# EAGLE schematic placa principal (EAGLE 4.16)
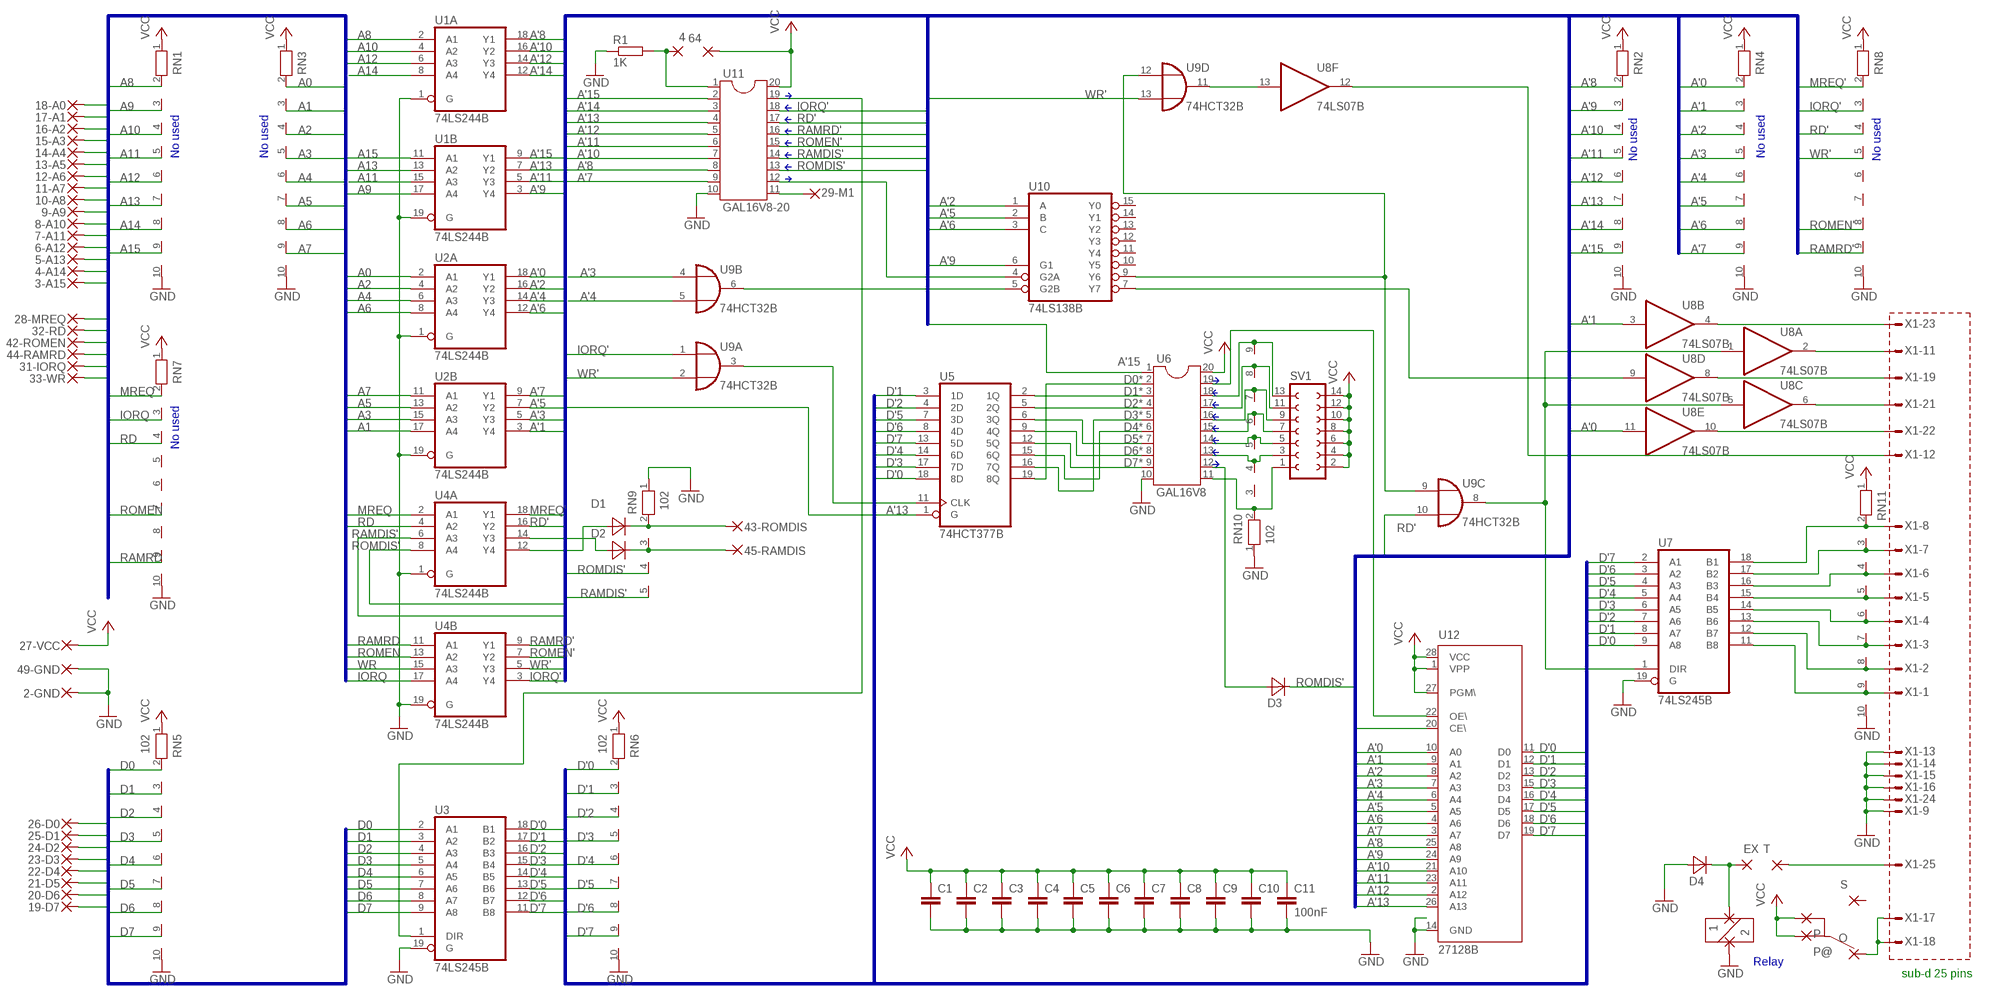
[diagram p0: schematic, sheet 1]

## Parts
1  1,27-REDONDO0.8  [1,27/0,8-REDONDO]
2  1,27-REDONDO0.8  [1,27/0,8-REDONDO]
2-GND  1,27-REDONDO0.8  [1,27/0,8-REDONDO]
3-A15  1,27-REDONDO0.8  [1,27/0,8-REDONDO]
4  1,27-REDONDO0.8  [1,27/0,8-REDONDO]
4-A14  1,27-REDONDO0.8  [1,27/0,8-REDONDO]
5-A13  1,27-REDONDO0.8  [1,27/0,8-REDONDO]
6-A12  1,27-REDONDO0.8  [1,27/0,8-REDONDO]
7-A11  1,27-REDONDO0.8  [1,27/0,8-REDONDO]
8-A10  1,27-REDONDO0.8  [1,27/0,8-REDONDO]
9-A9  1,27-REDONDO0.8  [1,27/0,8-REDONDO]
10-A8  1,27-REDONDO0.8  [1,27/0,8-REDONDO]
11-A7  1,27-REDONDO0.8  [1,27/0,8-REDONDO]
12-A6  1,27-REDONDO0.8  [1,27/0,8-REDONDO]
13-A5  1,27-REDONDO0.8  [1,27/0,8-REDONDO]
14-A4  1,27-REDONDO0.8  [1,27/0,8-REDONDO]
15-A3  1,27-REDONDO0.8  [1,27/0,8-REDONDO]
16-A2  1,27-REDONDO0.8  [1,27/0,8-REDONDO]
17-A1  1,27-REDONDO0.8  [1,27/0,8-REDONDO]
18-A0  1,27-REDONDO0.8  [1,27/0,8-REDONDO]
19-D7  1,27-REDONDO0.8  [1,27/0,8-REDONDO]
20-D6  1,27-REDONDO0.8  [1,27/0,8-REDONDO]
21-D5  1,27-REDONDO0.8  [1,27/0,8-REDONDO]
22-D4  1,27-REDONDO0.8  [1,27/0,8-REDONDO]
23-D3  1,27-REDONDO0.8  [1,27/0,8-REDONDO]
24-D2  1,27-REDONDO0.8  [1,27/0,8-REDONDO]
25-D1  1,27-REDONDO0.8  [1,27/0,8-REDONDO]
26-D0  1,27-REDONDO0.8  [1,27/0,8-REDONDO]
27-VCC  1,27-REDONDO0.8  [1,27/0,8-REDONDO]
28-MREQ  1,27-REDONDO0.8  [1,27/0,8-REDONDO]
29-M1  1,27-REDONDO0.8  [1,27/0,8-REDONDO]
31-IORQ  1,27-REDONDO0.8  [1,27/0,8-REDONDO]
32-RD  1,27-REDONDO0.8  [1,27/0,8-REDONDO]
33-WR  1,27-REDONDO0.8  [1,27/0,8-REDONDO]
42-ROMEN  1,27-REDONDO0.8  [1,27/0,8-REDONDO]
43-ROMDIS  1,27-REDONDO0.8  [1,27/0,8-REDONDO]
44-RAMRD  1,27-REDONDO0.8  [1,27/0,8-REDONDO]
45-RAMDIS  1,27-REDONDO0.8  [1,27/0,8-REDONDO]
49-GND  1,27-REDONDO0.8  [1,27/0,8-REDONDO]
64  1,27-REDONDO0.8  [1,27/0,8-REDONDO]
C1  C-EU050-024X044  [C050-024X044]
C2  C-EU050-024X044  [C050-024X044]
C3  C-EU050-024X044  [C050-024X044]
C4  C-EU050-024X044  [C050-024X044]
C5  C-EU050-024X044  [C050-024X044]
C6  C-EU050-024X044  [C050-024X044]
C7  C-EU050-024X044  [C050-024X044]
C8  C-EU050-024X044  [C050-024X044]
C9  C-EU050-024X044  [C050-024X044]
C10  C-EU050-024X044  [C050-024X044]
C11  100nF  C-EU050-024X044  [C050-024X044]
D1  DIODE-10/2  [D-10/2]
D2  DIODE-10/2  [D-10/2]
D3  DIODE-10/2  [D-10/2]
D4  DIODE-10/2  [D-10/2]
EX  1,27-REDONDO0.8  [1,27/0,8-REDONDO]
O  1,27-REDONDO0.8  [1,27/0,8-REDONDO]
P  1,27-REDONDO0.8  [1,27/0,8-REDONDO]
P@  1,27-REDONDO0.8  [1,27/0,8-REDONDO]
R1  1K  R-EU_0207/10  [0207/10]
RN1  RN091  [RN-101]
RN2  RN091  [RN-101]
RN3  RN091  [RN-101]
RN4  RN091  [RN-101]
RN5  102  RN091  [RN-101]
RN6  102  RN091  [RN-101]
RN7  RN091  [RN-101]
RN8  RN091  [RN-101]
RN9  102  RN041  [R-51]
RN10  102  RN081  [RN-91]
RN11  RN091  [RN-101]
S  1,27-REDONDO0.8  [1,27/0,8-REDONDO]
SV1  FE07-2  [FE07-2]
T  1,27-REDONDO0.8  [1,27/0,8-REDONDO]
U1  74LS244B  [DIL20-B]
U2  74LS244B  [DIL20-B]
U3  74LS245B  [DIL20-B]
U4  74LS244B  [DIL20-B]
U5  74HCT377B  [DIL20-B]
U6  GAL16V8  DIL20  [DIL20]
U7  74LS245B  [DIL20-B]
U8  74LS07B  [DIL14-B]
U9  74HCT32B  [DIL14-B]
U10  74LS138B  [DIL16-B]
U11  GAL16V8-20  DIL20  [DIL20]
U12  27128B  [DIL28-6B]
X1  M25HS  [M25H]

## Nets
A0: 18-A0.1(P) RN3.2 U2.2(A:A1)
A1: 17-A1.1(P) RN3.3 U2.17(B:A4)
A1'': U8.4(B:O) X1.23
A2: 16-A2.1(P) RN3.4 U2.4(A:A2)
A3: 15-A3.1(P) RN3.5 U2.15(B:A3)
A4: 14-A4.1(P) RN3.6 U2.6(A:A3)
A5: 13-A5.1(P) RN3.7 U2.13(B:A2)
A6: 12-A6.1(P) RN3.8 U2.8(A:A4)
A7: 11-A7.1(P) RN3.9 U2.11(B:A1)
A8: 10-A8.1(P) RN1.2 U1.2(A:A1)
A9: 9-A9.1(P) RN1.3 U1.17(B:A4)
A10: 8-A10.1(P) RN1.4 U1.4(A:A2)
A11: 7-A11.1(P) RN1.5 U1.15(B:A3)
A12: 6-A12.1(P) RN1.6 U1.6(A:A3)
A13: 5-A13.1(P) RN1.7 U1.13(B:A2)
A14: 4-A14.1(P) RN1.8 U1.8(A:A4)
A15: 3-A15.1(P) RN1.9 U1.11(B:A1)
A'0: RN4.2 U2.18(A:Y1) U8.11(E:I) U12.10(A0)
A'1: RN4.3 U2.3(B:Y4) U8.3(B:I) U12.9(A1)
A'2: RN4.4 U2.16(A:Y2) U10.1(A) U12.8(A2)
A'3: RN4.5 U2.5(B:Y3) U9.4(B:I0) U12.7(A3)
A'4: RN4.6 U2.14(A:Y3) U9.5(B:I1) U12.6(A4)
A'5: RN4.7 U2.7(B:Y2) U10.2(B) U12.5(A5)
A'6: RN4.8 U2.12(A:Y4) U10.3(C) U12.4(A6)
A'7: RN4.9 U2.9(B:Y1) U11.9 U12.3(A7)
A'8: RN2.2 U1.18(A:Y1) U11.8 U12.25(A8)
A'9: RN2.3 U1.3(B:Y4) U10.6(G1) U12.24(A9)
A'10: RN2.4 U1.16(A:Y2) U11.7 U12.21(A10)
A'11: RN2.5 U1.5(B:Y3) U11.6 U12.23(A11)
A'12: RN2.6 U1.14(A:Y3) U11.5 U12.2(A12)
A'13: RN2.7 U1.7(B:Y2) U5.1(G) U11.4 U12.26(A13)
A'14: RN2.8 U1.12(A:Y4) U11.3
A'15: RN2.9 U1.9(B:Y1) U6.1 U11.2
D0: 26-D0.1(P) RN5.2 U3.2(A1)
D0*: U5.19(8Q) U6.2
D1: 25-D1.1(P) RN5.3 U3.3(A2)
D1*: U5.2(1Q) U6.3
D2: 24-D2.1(P) RN5.4 U3.4(A3)
D2*: U5.5(2Q) U6.4
D3: 23-D3.1(P) RN5.5 U3.5(A4)
D3*: U5.16(7Q) U6.5
D4: 22-D4.1(P) RN5.6 U3.6(A5)
D4*: U5.15(6Q) U6.6
D5: 21-D5.1(P) RN5.7 U3.7(A6)
D5*: U5.6(3Q) U6.7
D6: 20-D6.1(P) RN5.8 U3.8(A7)
D6*: U5.9(4Q) U6.8
D7: 19-D7.1(P) RN5.9 U3.9(A8)
D7*: U5.12(5Q) U6.9
D'0: RN6.2 U3.18(B1) U5.18(8D) U7.9(A8) U12.11(D0)
D'1: RN6.3 U3.17(B2) U5.3(1D) U7.8(A7) U12.12(D1)
D'2: RN6.4 U3.16(B3) U5.4(2D) U7.7(A6) U12.13(D2)
D'3: RN6.5 U3.15(B4) U5.17(7D) U7.6(A5) U12.15(D3)
D'4: RN6.6 U3.14(B5) U5.14(6D) U7.5(A4) U12.16(D4)
D'5: RN6.7 U3.13(B6) U5.7(3D) U7.4(A3) U12.17(D5)
D'6: RN6.8 U3.12(B7) U5.8(4D) U7.3(A2) U12.18(D6)
D'7: RN6.9 U3.11(B8) U5.13(5D) U7.2(A1) U12.19(D7)
DIR: U7.1(DIR) U8.1(A:I) U8.5(C:I) U9.8(C:O)
DIR': U8.2(A:O) X1.11
GND: 2-GND.1(P) 2.1(P) 49-GND.1(P) C1.2 C2.2 C3.2 C4.2 C5.2 C6.2 C7.2 C8.2 C9.2 C10.2 C11.2 D4.P$3(A) R1.1 RN1.10 RN2.10 RN3.10 RN4.10 RN5.10 RN6.10 RN7.10 RN8.10 RN9.1 RN10.1 RN11.10 U1.1(A:G) U1.19(B:G) U2.1(A:G) U2.19(B:G) U3.19(G) U4.1(A:G) U4.19(B:G) U6.10 U7.19(G) U11.10 U12.14(GND) X1.9 X1.13 X1.14 X1.15 X1.16 X1.24
IORQ: 31-IORQ.1(P) RN7.3 U4.17(B:A4)
IORQ': RN8.3 U4.3(B:Y4) U9.1(A:I0) U11.18
M1: 29-M1.1(P) U11.11
MREQ: 28-MREQ.1(P) RN7.2 U4.2(A:A1)
MREQ': RN8.2 U4.18(A:Y1)
N$2: U9.6(B:O) U10.5(G2B)
N$3: 4.1(P) R1.2 U11.1
N$4: U3.1(DIR) U11.19
N$5: U10.4(G2A) U11.12
N$6: D2.P$3(A) U4.14(A:Y3)
N$7: D1.P$3(A) U4.12(A:Y4)
N$8: U8.9(D:I) U10.7(Y7)
N$9: U5.11(CLK) U9.3(A:O)
N$10: U8.6(C:O) X1.21
N$11: U9.9(C:I0) U9.12(D:I0) U10.9(Y6)
N$13: U8.13(F:I) U9.11(D:O)
N$14: U8.8(D:O) X1.19
N$15: U8.10(E:O) X1.22
N$16: U8.12(F:O) X1.12
N$17: D3.P$3(A) U6.12
N$18: U6.19 U12.22(OE\)
N$19: RN10.4 SV1.3 U6.13
N$20: RN10.5 SV1.5 U6.14
N$21: RN10.6 SV1.7 U6.15
N$22: RN10.7 SV1.9 U6.16
N$23: RN10.8 SV1.11 U6.17
N$24: RN10.9 SV1.13 U6.18
N$25: RN10.2 SV1.1 U6.11
N$26: RN11.9 U7.11(B8) X1.1
N$27: RN11.8 U7.12(B7) X1.2
N$28: RN11.7 U7.13(B6) X1.3
N$29: RN11.6 U7.14(B5) X1.4
N$30: RN11.5 U7.15(B4) X1.5
N$31: RN11.4 U7.16(B3) X1.6
N$32: RN11.3 U7.17(B2) X1.7
N$33: RN11.2 U7.18(B1) X1.8
N$34: O.1(P) X1.17 X1.18
N$35: 1.1(P) D4.P$4(K) EX.1(P)
N$36: T.1(P) X1.25
RAMDIS: 45-RAMDIS.1(P) D2.P$4(K) RN9.3
RAMDIS': RN9.5 U4.6(A:A3) U11.14
RAMRD: 44-RAMRD.1(P) RN7.9 U4.11(B:A1)
RAMRD': RN8.9 U4.9(B:Y1) U11.16
RD: 32-RD.1(P) RN7.4 U4.4(A:A2)
RD': RN8.4 U4.16(A:Y2) U9.10(C:I1) U11.17
ROMDIS: 43-ROMDIS.1(P) D1.P$4(K) RN9.2
ROMDIS': D3.P$4(K) RN9.4 U4.8(A:A4) U11.13
ROMEN: 42-ROMEN.1(P) RN7.7 U4.13(B:A2)
ROMEN': RN8.8 U4.7(B:Y2) U11.15 U12.20(CE\)
VCC: 27-VCC.1(P) 64.1(P) C1.1 C2.1 C3.1 C4.1 C5.1 C6.1 C7.1 C8.1 C9.1 C10.1 C11.1 P.1(P) P@.1(P) RN1.1 RN2.1 RN3.1 RN4.1 RN5.1 RN6.1 RN7.1 RN8.1 RN11.1 SV1.2 SV1.4 SV1.6 SV1.8 SV1.10 SV1.12 SV1.14 U6.20 U11.20 U12.1(VPP) U12.27(PGM\) U12.28(VCC)
WR: 33-WR.1(P) U4.15(B:A3)
WR': RN8.5 U4.5(B:Y3) U9.2(A:I1) U9.13(D:I1)
Unconnected: RN7.5 RN7.6 RN7.8 RN8.6 RN8.7 RN10.3 S.1(P) U10.10(Y5) U10.11(Y4) U10.12(Y3) U10.13(Y2) U10.14(Y1) U10.15(Y0) X1.10 X1.20

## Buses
A'[0..15],MREQ',RD',ROMEN',RAMRD',IORQ',WR',RAMDIS',ROMDIS'
D[0..7]
A[0..15],MREQ,RD,ROMEN,RAMRD,IORQ,WR,D[0..7]
D'[0..7]
B$1
B$2
B$3
B$4
B$5
B$6
B$7
B$8
B$9
B$10
B$11
B$12
B$13
B$14
B$15
B$16

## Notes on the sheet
- No used | No used | No used | No used | No used
- No used
- Relay
- sub-d 25 pins

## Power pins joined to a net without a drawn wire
GND: U1.10(P:GND) U2.10(P:GND) U3.10(GND) U4.10(P:GND) U5.10(GND) U7.10(GND) U8.7(P:GND) U9.7(P:GND) U10.8(GND)
VCC: U1.20(P:VCC) U2.20(P:VCC) U3.20(VCC) U4.20(P:VCC) U5.20(VCC) U7.20(VCC) U8.14(P:VCC) U9.14(P:VCC) U10.16(VCC)

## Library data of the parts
1 2 2-GND 3-A15 4 4-A14 5-A13 6-A12 7-A11 8-A10 9-A9 10-A8 11-A7 12-A6 13-A5 14-A4 15-A3 16-A2 17-A1 18-A0 19-D7 20-D6 21-D5 22-D4 23-D3 24-D2 25-D1 26-D0 27-VCC 28-MREQ 29-M1 31-IORQ 32-RD 33-WR 42-ROMEN 43-ROMDIS 44-RAMRD 45-RAMDIS 49-GND 64 EX O P P@ S T = wirepad2:1,27-REDONDO
C1-C11 = rcl:C-EU: CAPACITOR, European symbol
D1-D4 = discrete2:DIODE-10/2
R1 = rcl:R-EU_: RESISTOR, European symbol
RN1-RN8 RN11 = discrete2:RN09
RN9 = discrete2:RN04
RN10 = discrete2:RN08
SV1 = con-lsta:FE07-2: FEMALE HEADER
U1 U2 U4 = 74xx-eu2:74*244: Octal BUFFER and LINE DRIVER, 3-state
U3 U7 = 74xx-eu2:74*245: Octal BUS TRANSCEIVER, 3-state
U5 = 74xx-eu2:74*377: Octal D type FLIP FLOP, enable
U6 U11 = dil2:DIL20: SOCKET Dual In Line
U8 = 74xx-eu2:74*07: Hex BUFFER, open collector high-voltage output
U9 = 74xx-eu2:74*32: Quad 2-input OR gate
U10 = 74xx-eu2:74*138: 3-line to 8-line DECODER/DEMULTIPLEXER
U12 = microchip:27*128: CMOS EPROM 128 K (16 K x 8)
X1 = con-subd:M25?S: SUB-D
